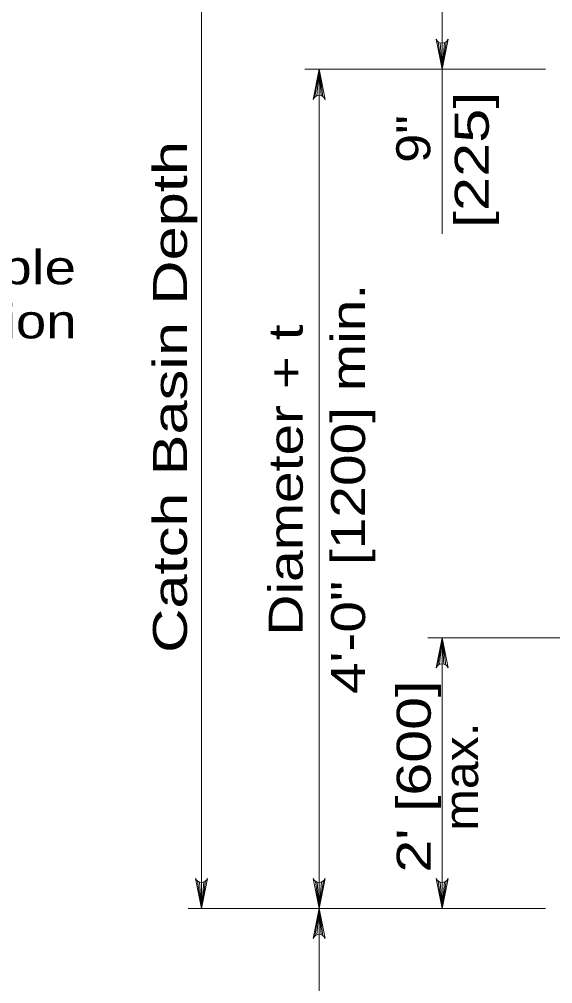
# Model space of a CAD drawing. Extents: x 1073.4 to 1107.4, y 719.4 to 741.4.
# Drawn here: x 1084.722 to 1087.233, y 723.691 to 728.228 of the extents above; entities that cross this region are included whole.
import ezdxf
from ezdxf.enums import TextEntityAlignment as Align

# ---------------------------------------------------------------- set-up
doc = ezdxf.new("R2010")
doc.units = 0
doc.header["$LTSCALE"] = 0.062
doc.layers.add('1', color=7, linetype='Continuous', lineweight=13)

msp = doc.modelspace()

# ---------------------------------------------------------------- linework, layer by layer
at = {"layer": '1'}
for p, q in [((1086.71208, 727.21808), (1086.71208, 728.44875)), ((1085.57925, 728.38208), (1085.57925, 724.04508)), ((1086.69417, 728.121), (1086.71208, 727.99275)), ((1086.703, 728.11667), (1086.71208, 727.99275)), ((1086.73183, 728.1225), (1086.71208, 727.99275)), ((1086.72358, 728.11758), (1086.71208, 727.99275)), ((1086.71208, 728.11533), (1086.71208, 727.99275)), ((1087.1995, 727.99275), (1086.06683, 727.99275)), ((1086.11358, 727.86308), (1086.1335, 727.99275)), ((1086.12192, 727.868), (1086.1335, 727.99275)), ((1086.1335, 727.87025), (1086.1335, 727.99275)), ((1086.14258, 727.86892), (1086.1335, 727.99275)), ((1086.15142, 727.86458), (1086.1335, 727.99275)), ((1086.1335, 724.04508), (1086.1335, 727.99275)), ((1086.64542, 725.31842), (1087.30583, 725.31842)), ((1086.69225, 725.18875), (1086.712, 725.31842)), ((1086.7005, 725.19367), (1086.712, 725.31842)), ((1086.712, 724.04508), (1086.712, 725.31842)), ((1086.712, 725.19592), (1086.712, 725.31842)), ((1086.72108, 725.19458), (1086.712, 725.31842)), ((1086.72992, 725.19025), (1086.712, 725.31842)), ((1085.56125, 724.17325), (1085.57925, 724.04508)), ((1085.57017, 724.16892), (1085.57925, 724.04508)), ((1085.59908, 724.17475), (1085.57925, 724.04508)), ((1085.59075, 724.16983), (1085.57925, 724.04508)), ((1085.57925, 724.16758), (1085.57925, 724.04508)), ((1086.11558, 724.17325), (1086.1335, 724.04508)), ((1086.12442, 724.16892), (1086.1335, 724.04508)), ((1086.15325, 724.17475), (1086.1335, 724.04508)), ((1086.145, 724.16983), (1086.1335, 724.04508)), ((1086.1335, 724.16758), (1086.1335, 724.04508)), ((1086.69408, 724.17325), (1086.712, 724.04508)), ((1086.70292, 724.16892), (1086.712, 724.04508)), ((1086.73192, 724.17475), (1086.712, 724.04508)), ((1086.72358, 724.16983), (1086.712, 724.04508)), ((1086.712, 724.16758), (1086.712, 724.04508)), ((1085.51625, 724.04508), (1087.1995, 724.04508)), ((1086.11358, 723.91533), (1086.1335, 724.04508)), ((1086.12192, 723.92025), (1086.1335, 724.04508)), ((1086.1335, 724.04508), (1086.1335, 721.93425)), ((1086.1335, 723.9225), (1086.1335, 724.04508)), ((1086.14258, 723.92117), (1086.1335, 724.04508)), ((1086.15142, 723.91683), (1086.1335, 724.04508))]:
    msp.add_line(p, q, dxfattribs=at)
for points in [[(1086.74042, 728.13442), (1086.71208, 727.99275), (1086.68375, 728.13442)], [(1086.10517, 727.85117), (1086.1335, 727.99275), (1086.16183, 727.85117)], [(1086.68367, 725.17683), (1086.712, 725.31842), (1086.74033, 725.17683)], [(1085.60758, 724.18667), (1085.57925, 724.04508), (1085.55092, 724.18667)], [(1086.16183, 724.18667), (1086.1335, 724.04508), (1086.10517, 724.18667)], [(1086.74033, 724.18667), (1086.712, 724.04508), (1086.68367, 724.18667)], [(1086.10517, 723.90342), (1086.1335, 724.04508), (1086.16183, 723.90342)]]:
    msp.add_lwpolyline(points, dxfattribs=at)
for centre, start, end in [((1086.71202, 728.14581), 202.08782, 337.91395), ((1086.1335, 727.83974), 22.08782, 157.91395), ((1086.71206, 725.16542), 22.08782, 157.91395), ((1085.5792, 724.19809), 202.08782, 337.91395), ((1086.13344, 724.19809), 202.08782, 337.91395), ((1086.712, 724.19809), 202.08782, 337.91395), ((1086.1335, 723.89202), 22.08782, 157.91395)]:
    msp.add_arc(centre, 0.03056, start, end, dxfattribs=at)

# ---------------------------------------------------------------- texts
for s, width, p in [('[225]', 1.35, (1086.93192, 727.56675)), ('9"', 1.15, (1086.65633, 727.66475)), ('4\'-0" [1200] min.', 1.25, (1086.34975, 726.01867)), ('Diameter + t', 1.25, (1086.05608, 726.06042)), ("2' [600]", 1.3, (1086.65867, 724.66542)), ('max.', 1.1, (1086.88158, 724.66542))]:
    msp.add_text(s, height=0.16, rotation=90, dxfattribs=dict(at, width=width)).set_placement(p, align=Align.CENTER)
at = {"layer": '1', "width": 1.35}
msp.add_text('Catch Basin Depth', height=0.16, rotation=90, dxfattribs=at).set_placement((1085.51142, 725.24717))
at = {"layer": '1'}
for s, width, p in [('Permissible', 1.25, (1083.60733, 726.98125)), ('construction', 1.2, (1083.60733, 726.72683))]:
    msp.add_text(s, height=0.16, dxfattribs=dict(at, width=width)).set_placement(p)

doc.saveas('drawing.dxf')
